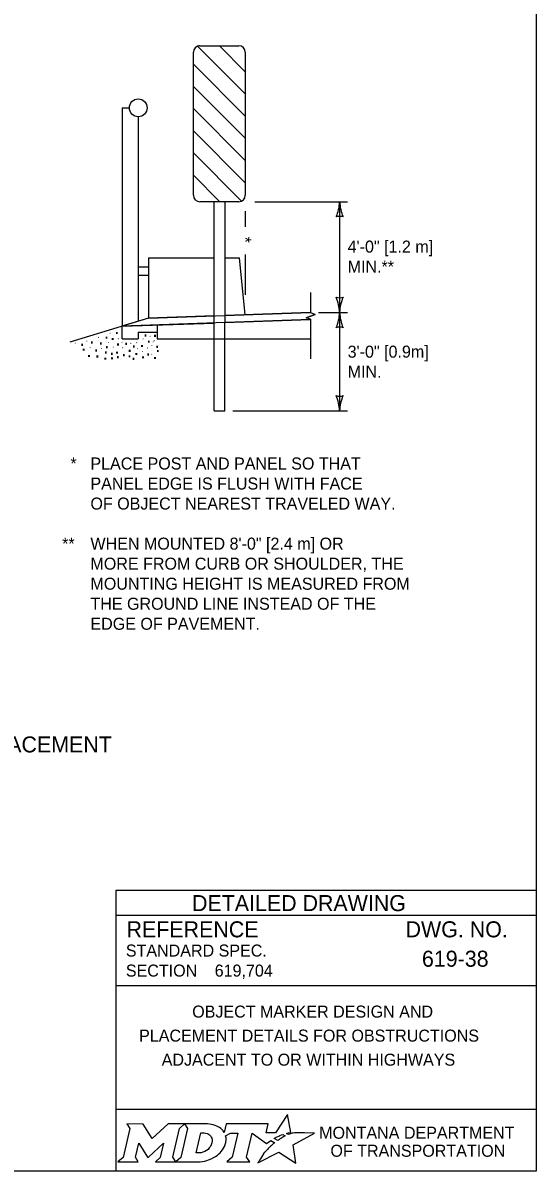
# Model space of a CAD drawing. Extents: x 49991.4 to 50021, y 49987.6 to 50011.4.
# Drawn here: x 50014.19 to 50016.75, y 49987.8 to 49993.53 of the extents above; entities that cross this region are included whole.
import ezdxf

# ---------------------------------------------------------------- set-up
doc = ezdxf.new("R2010")
doc.units = 0
for name, color, linetype in [('Default', 7, 'Continuous'), ('Level 1', 7, 'Continuous'), ('Level 2', 7, 'Continuous'), ('Level 3', 7, 'Continuous'), ('Level 4', 7, 'Continuous'), ('Level 5', 7, 'Continuous'), ('Level 6', 7, 'Continuous')]:
    doc.layers.add(name, color=color, linetype=linetype)

msp = doc.modelspace()

# ---------------------------------------------------------------- linework, layer by layer
at = {"layer": 'Default'}
for points in [[(50015.5126, 49987.9811), (50015.5023, 49987.9867), (50015.5139, 49987.9895), (50015.5255, 49987.9915), (50015.5081, 49988.0816), (50015.4486, 49987.9903), (50015.4013, 49987.9896), (50015.4116, 49988.0337), (50015.2024, 49988.0338), (50015.1923, 49987.9913), (50015.1865, 49987.9996)], [(50014.7056, 49988.0338), (50014.7197, 49988.0104), (50014.6862, 49987.8671), (50014.6605, 49987.8446), (50014.7621, 49987.8446), (50014.7486, 49987.8674), (50014.7648, 49987.9375), (50014.8085, 49987.8685), (50014.8138, 49987.8685), (50014.8889, 49987.938), (50014.8725, 49987.8669), (50014.8478, 49987.8449), (50014.9494, 49987.8449), (50014.9356, 49987.8682), (50014.9688, 49988.0106)], [(50014.9688, 49988.0106), (50014.9941, 49988.0338), (50014.9117, 49988.0338), (50014.8321, 49987.9608), (50014.7876, 49988.0335), (50014.7056, 49988.0338)], [(50015.1077, 49988.0338), (50014.9941, 49988.0338), (50015.0088, 49988.0109), (50014.9749, 49987.8671), (50014.9494, 49987.8449), (50015.06, 49987.8449)], [(50015.1317, 49987.9471), (50015.1305, 49987.939), (50015.1273, 49987.9297), (50015.1231, 49987.9215), (50015.1175, 49987.914), (50015.111, 49987.9071), (50015.1031, 49987.9008), (50015.0948, 49987.8961), (50015.0857, 49987.8922), (50015.0766, 49987.8899), (50015.0674, 49987.889), (50015.0515, 49987.889), (50015.0751, 49987.989), (50015.0911, 49987.989), (50015.0987, 49987.9884), (50015.1063, 49987.9865), (50015.1129, 49987.9835), (50015.119, 49987.9793), (50015.1238, 49987.9743), (50015.1275, 49987.9683), (50015.1302, 49987.9621), (50015.1318, 49987.9547), (50015.1318, 49987.9517), (50015.1317, 49987.9471)], [(50015.1991, 49987.9747), (50015.2237, 49987.9878), (50015.2606, 49987.9878), (50015.232, 49987.8673), (50015.2045, 49987.8446), (50015.3207, 49987.8446), (50015.3037, 49987.8675), (50015.3319, 49987.9877), (50015.4032, 49987.936), (50015.4243, 49987.9511), (50015.444, 49987.9402)], [(50015.3882, 49987.8843), (50015.3729, 49987.8599), (50015.3682, 49987.8524), (50015.3624, 49987.8438), (50015.3601, 49987.8395), (50015.4654, 49987.8926), (50015.5493, 49987.8375), (50015.5362, 49987.9302), (50015.6431, 49987.9886), (50015.5938, 49987.9894), (50015.5637, 49987.9898), (50015.5429, 49987.9901), (50015.5361, 49987.9886), (50015.5312, 49987.9874), (50015.5228, 49987.9851), (50015.5126, 49987.9811)], [(50015.4622, 49987.9535), (50015.4598, 49987.9518), (50015.4415, 49987.9614), (50015.4518, 49987.9671), (50015.4559, 49987.9693), (50015.4645, 49987.9733), (50015.4702, 49987.9759), (50015.4781, 49987.9789), (50015.4854, 49987.9816), (50015.4972, 49987.9742), (50015.4932, 49987.9721), (50015.4886, 49987.9696), (50015.4844, 49987.9674), (50015.4794, 49987.9645), (50015.4775, 49987.9634), (50015.4748, 49987.9618), (50015.4723, 49987.9604), (50015.47, 49987.9588), (50015.4674, 49987.957), (50015.4647, 49987.9552), (50015.4622, 49987.9535)], [(50015.4021, 49987.9004), (50015.4021, 49987.9004)], [(50015.1057, 49987.8522), (50015.1141, 49987.8548), (50015.1271, 49987.8602), (50015.1475, 49987.8712)]]:
    msp.add_lwpolyline(points, dxfattribs=at)
for centre, radius, start, end in [((50015.1308, 49987.9554), 0.0709, 339.53292, 15.85821), ((50015.0868, 49987.9727), 0.1183, 300.91025, 339.13831)]:
    msp.add_arc(centre, radius, start, end, dxfattribs=at)
for centre, major_axis, ratio, start_param, end_param in [((50015.1056, 49987.9864), (0.0834, -0.0037), 0.568097, 0.61298, 1.570796), ((50015.1612, 49987.9937), (0.0361, -0.0295), 0.469099, 1.225588, 1.570796), ((50015.3952, 49987.8923), (-0.00694, -0.00806), 0.008222, 0, 3.137361), ((50015.4119, 49987.9106), (-0.0098, -0.0102), 0.016458, 3.141593, 6.279097), ((50015.4329, 49987.9305), (-0.0112, -0.0097), 0.021651, 3.157348, 6.283185), ((50015.0603, 49987.9932), (0, 0.1484), 0.987302, 3.139398, 3.456847)]:
    msp.add_ellipse(centre, major_axis=major_axis, ratio=ratio, start_param=start_param, end_param=end_param, dxfattribs=at)
at = {"layer": 'Level 1'}
for p, q in [((50015.2973, 49993.1754), (50015.0589, 49993.4137)), ((50015.0703, 49993.4158), (50015.1676, 49993.4159)), ((50015.0703, 49993.4158), (50015.2649, 49993.4158)), ((50015.1676, 49993.4159), (50015.2973, 49993.2863)), ((50015.0379, 49992.67), (50015.0379, 49993.3834)), ((50015.2973, 49993.3834), (50015.2973, 49992.67)), ((50015.0379, 49993.2131), (50015.0379, 49993.324)), ((50015.0379, 49993.324), (50015.2973, 49993.0648)), ((50015.2973, 49993.2863), (50015.2973, 49993.1754)), ((50015.2973, 49992.9538), (50015.0379, 49993.2131)), ((50014.682, 49993.106), (50014.7179, 49993.106)), ((50014.682, 49993.106), (50014.682, 49992.0164)), ((50014.7622, 49993.0617), (50014.7622, 49992.0407)), ((50015.0379, 49992.9914), (50015.0379, 49993.1023)), ((50015.0379, 49993.1023), (50015.2973, 49992.843)), ((50015.2973, 49993.0648), (50015.2973, 49992.9538)), ((50015.2973, 49992.7321), (50015.0379, 49992.9914)), ((50015.0379, 49992.7698), (50015.0379, 49992.8807)), ((50015.0379, 49992.8807), (50015.2781, 49992.6404)), ((50015.2973, 49992.843), (50015.2973, 49992.7321)), ((50015.1703, 49992.6375), (50015.0379, 49992.7698)), ((50015.2649, 49992.6376), (50015.0703, 49992.6376)), ((50015.1418, 49992.0319), (50015.1418, 49992.6376)), ((50015.2649, 49992.6376), (50015.1703, 49992.6375)), ((50015.1947, 49992.6375), (50015.1947, 49992.0338)), ((50014.8133, 49992.311), (50014.7622, 49992.311)), ((50014.8133, 49992.3578), (50014.8133, 49992.0562)), ((50014.8133, 49992.3578), (50015.1418, 49992.3578)), ((50015.1947, 49992.3578), (50015.2682, 49992.3578)), ((50015.2973, 49992.073), (50015.2682, 49992.3578)), ((50014.8133, 49992.2695), (50014.7622, 49992.2695)), ((50014.8134, 49992.0562), (50015.6236, 49992.0844)), ((50015.6236, 49992.0844), (50015.1947, 49992.0695)), ((50015.6236, 49992.0828), (50015.6236, 49992.0844)), ((50015.6464, 49992.0747), (50015.6236, 49992.0828)), ((50014.8134, 49992.0562), (50014.4205, 49991.9371)), ((50014.8134, 49992.0562), (50014.6804, 49992.0159)), ((50015.6236, 49992.0487), (50014.6804, 49992.0159)), ((50014.6804, 49992.0159), (50015.1418, 49992.0319)), ((50015.1418, 49992.0676), (50014.8134, 49992.0562)), ((50015.1418, 49992.0319), (50015.1418, 49992.0676)), ((50015.1947, 49992.0695), (50015.1947, 49992.0338)), ((50015.1947, 49992.0338), (50015.6236, 49992.0487)), ((50015.6008, 49992.0585), (50015.6236, 49992.0666)), ((50015.6236, 49992.0504), (50015.6008, 49992.0585)), ((50015.6236, 49992.0666), (50015.6464, 49992.0747)), ((50015.6236, 49992.0487), (50015.6236, 49992.0504))]:
    msp.add_line(p, q, dxfattribs=at)
msp.add_lwpolyline([(49999.3835, 49998.9992), (50016.7501, 49998.9992), (50016.7501, 49987.7988), (49999.3835, 49987.7988)], close=True, dxfattribs=at)
msp.add_circle((50014.7622, 49993.106), 0.0443, dxfattribs=at)
for centre, start, end in [((50015.0703, 49993.3834), 90.04393, 180), ((50015.0703, 49993.3834), 90, 110.61491), ((50015.2649, 49993.3834), 0, 90), ((50015.0703, 49992.67), 180, 270), ((50015.2649, 49992.67), 270.04406, 0), ((50015.2649, 49992.67), 270, 294.15631)]:
    msp.add_arc(centre, 0.0324, start, end, dxfattribs=at)
at = {"layer": 'Level 3'}
for p, q in [((50015.345, 49992.6375), (50015.8087, 49992.6375)), ((50015.7687, 49992.6375), (50015.7687, 49992.0844)), ((50015.2973, 49992.59), (50015.2973, 49992.5125)), ((50015.2973, 49992.3739), (50015.2973, 49992.173)), ((50015.6636, 49992.0844), (50015.8087, 49992.0844)), ((50015.7687, 49992.0844), (50015.7687, 49991.5934)), ((50015.2347, 49991.5934), (50015.8087, 49991.5934))]:
    msp.add_line(p, q, dxfattribs=at)
for centre, radius, start, end in [((50015.5466, 49992.6467), 0.2223, 337.45601, 357.63952), ((50016.0014, 49992.649), 0.233, 182.82731, 202.07716), ((50015.7687, 49992.5093), 0.0548, 72.13882, 107.86118), ((50015.7687, 49992.2126), 0.0548, 252.13882, 287.86118), ((50015.536, 49992.0729), 0.233, 2.82731, 22.07716), ((50015.9908, 49992.0752), 0.2223, 157.45601, 177.63952), ((50015.5466, 49992.0936), 0.2223, 337.45601, 357.63952), ((50016.0014, 49992.0959), 0.233, 182.82731, 202.07716), ((50015.7687, 49991.9562), 0.0548, 72.13882, 107.86118), ((50015.7687, 49991.7216), 0.0548, 252.13882, 287.86118), ((50015.536, 49991.5819), 0.233, 2.82731, 22.07716), ((50015.9908, 49991.5842), 0.2223, 157.45601, 177.63952)]:
    msp.add_arc(centre, radius, start, end, dxfattribs=at)
at = {"layer": 'Level 4'}
for p, q in [((50014.8562, 49992.022), (50014.8562, 49991.9529)), ((50015.1418, 49991.5934), (50015.1418, 49992.0319)), ((50015.1947, 49991.5934), (50015.1947, 49992.0338)), ((50014.682, 49991.9529), (50014.682, 49992.016)), ((50014.7622, 49991.9861), (50014.7622, 49991.9529)), ((50014.7622, 49991.9861), (50014.8562, 49991.9861)), ((50014.682, 49991.9529), (50014.7622, 49991.9529)), ((50014.8562, 49991.9529), (50015.6236, 49991.9529)), ((50015.1418, 49991.5934), (50015.1947, 49991.5934))]:
    msp.add_line(p, q, dxfattribs=at)
at = {"layer": 'Level 5'}
for p, q in [((50016.7501, 49989.1988), (50014.6501, 49989.1988)), ((50014.6501, 49989.1988), (50014.6501, 49987.7988)), ((50016.7501, 49989.0738), (50014.6501, 49989.0738)), ((50016.3862, 49988.8587), (50016.3862, 49988.8587)), ((50015.1444, 49988.7993), (50015.1444, 49988.7993)), ((50016.7501, 49988.7238), (50014.6501, 49988.7238)), ((50015.7001, 49988.4747), (50015.7001, 49988.4747)), ((50016.7501, 49988.1057), (50014.6501, 49988.1057))]:
    msp.add_line(p, q, dxfattribs=at)
at = {"layer": 'Level 6'}
for p, q in [((50015.6236, 49992.1844), (50015.6236, 49992.0828)), ((50015.6464, 49992.0747), (50015.6236, 49992.0828)), ((50015.6236, 49992.0666), (50015.6008, 49992.0585)), ((50015.6236, 49992.0504), (50015.6008, 49992.0585)), ((50015.6464, 49992.0747), (50015.6236, 49992.0666)), ((50015.6236, 49992.0504), (50015.6236, 49991.8529))]:
    msp.add_line(p, q, dxfattribs=at)

# ---------------------------------------------------------------- texts
at = {"layer": 'Default'}
for s, p in [('MONTANA DEPARTMENT', (50015.6663, 49987.96)), ('OF TRANSPORTATION', (50015.7225, 49987.87))]:
    msp.add_text(s, height=0.06, dxfattribs=at).set_placement(p)
at = {"layer": 'Level 1'}
for p in [(50014.5907, 49991.953), (50014.6421, 49991.9767), (50014.7857, 49991.9643), (50014.8329, 49991.9623), (50014.4686, 49991.9171), (50014.5169, 49991.9294), (50014.562, 49991.9243), (50014.5928, 49991.9058), (50014.6215, 49991.9469), (50014.6482, 49991.9192), (50014.6893, 49991.9223), (50014.7272, 49991.9089), (50014.7683, 49991.912), (50014.8022, 49991.9335), (50014.8442, 49991.9079), (50014.4768, 49991.8935), (50014.5035, 49991.8617), (50014.5394, 49991.8894), (50014.545, 49991.8594), (50014.5846, 49991.8484), (50014.5869, 49991.8789), (50014.6174, 49991.873), (50014.6184, 49991.8499), (50014.6431, 49991.8781), (50014.6475, 49991.8561), (50014.677, 49991.8658), (50014.7061, 49991.8599), (50014.7067, 49991.8874), (50014.7252, 49991.8473), (50014.7396, 49991.872), (50014.7733, 49991.8551), (50014.7991, 49991.8689), (50014.8329, 49991.8518), (50014.8467, 49991.887)]:
    msp.add_text('.', height=0.07, dxfattribs=at).set_placement(p)
for p in [(50014.616, 49991.9836), (50014.8162, 49991.9684), (50014.4416, 49991.9336), (50014.5007, 49991.9441), (50014.5159, 49991.9117), (50014.5583, 49991.9627), (50014.5731, 49991.9069), (50014.6074, 49991.9365), (50014.6317, 49991.9145), (50014.657, 49991.955), (50014.6761, 49991.9388), (50014.6789, 49991.9102), (50014.7194, 49991.9326), (50014.7495, 49991.936), (50014.7533, 49991.9055), (50014.7809, 49991.9546), (50014.8033, 49991.9098), (50014.8252, 49991.9222), (50014.8305, 49991.9398), (50014.8362, 49991.946), (50014.7776, 49991.8921), (50014.8242, 49991.8779)]:
    msp.add_text('.', height=0.03, rotation=315, dxfattribs=at).set_placement(p)
at = {"layer": 'Level 2'}
for s, rotation, p in [('*', 270, (50015.2673, 49992.4631)), ('4\'-0" [1.2 m]', 0.02928, (50015.8087, 49992.3832)), ('MIN.**', 0.02928, (50015.8087, 49992.2832)), ('3\'-0" [0.9m]', 0.02928, (50015.8087, 49991.8588)), ('MIN.', 0.02928, (50015.8087, 49991.7588))]:
    msp.add_text(s, height=0.06, rotation=rotation, dxfattribs=at).set_placement(p)
for s, height, p in [('*', 0.06, (50014.4237, 49991.3006)), ('PLACE POST AND PANEL SO THAT', 0.06, (50014.5234, 49991.3006)), ('PANEL EDGE IS FLUSH WITH FACE', 0.06, (50014.5234, 49991.2006)), ('OF OBJECT NEAREST TRAVELED WAY.', 0.06, (50014.5234, 49991.1006)), ('**', 0.06, (50014.3821, 49990.9006)), ('WHEN MOUNTED 8\'-0" [2.4 m] OR ', 0.06, (50014.5234, 49990.9006)), ('MORE FROM CURB OR SHOULDER, THE', 0.06, (50014.5234, 49990.8006)), ('MOUNTING HEIGHT IS MEASURED FROM', 0.06, (50014.5234, 49990.7006)), ('THE GROUND LINE INSTEAD OF THE', 0.06, (50014.5234, 49990.6006)), ('EDGE OF PAVEMENT.', 0.06, (50014.5234, 49990.5006)), ('TYPICAL USE AND PLACEMENT', 0.08, (50012.9958, 49989.8882)), ('619-38', 0.08, (50016.1798, 49988.8187)), ('619,704', 0.06, (50015.1444, 49988.7693)), ('OBJECT MARKER DESIGN AND', 0.06, (50015.0319, 49988.5647)), ('PLACEMENT DETAILS FOR OBSTRUCTIONS', 0.06, (50014.7666, 49988.4447)), ('ADJACENT TO OR WITHIN HIGHWAYS ', 0.06, (50014.8795, 49988.3247))]:
    msp.add_text(s, height=height, dxfattribs=at).set_placement(p)
at = {"layer": 'Level 5'}
for s, height, p in [('DETAILED DRAWING', 0.0799, (50015.0311, 49989.0963)), ('REFERENCE', 0.08, (50014.7037, 49988.9654)), ('DWG. NO.', 0.08, (50016.0979, 49988.9654)), ('STANDARD SPEC.', 0.06, (50014.7004, 49988.8694)), ('SECTION', 0.06, (50014.7004, 49988.7694))]:
    msp.add_text(s, height=height, dxfattribs=at).set_placement(p)

doc.saveas('drawing.dxf')
